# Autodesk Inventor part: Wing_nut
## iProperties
Shininess: 41.0
Length Units: 11269
Angle Units: 11279
Time Units: 11290
Mass Units: 11283
Length Display Precision: 3
Angle Display Precision: 2
Created: 2001-04
Part Number: Wing_nut
Material: Standard
Document SubType Name: Modellieren
Designer: dl
Density: 0.0
Volumn: 0.0
Area: 0.0
PropertySet Name: Model Information
Control State: 0
Master: False
Checked Out: False
Author: dl
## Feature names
1. Extrusion1
2. Extrusion2
3. Mirror1
4. Mirror2
5. Extrusion3
6. Extrusion4
7. Hole1
8. Revolution1
9. Fillet1
10. Fillet2
11. Fillet3
